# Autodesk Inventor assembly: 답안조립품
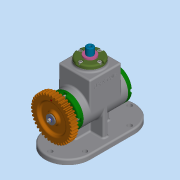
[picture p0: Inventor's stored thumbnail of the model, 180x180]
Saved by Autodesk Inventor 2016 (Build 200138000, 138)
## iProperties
Created: 2020-01
Part Number: 답안조립품
Document SubType Name: Assembly
Designer: MIRAE
Mass: 2018.69 g
Surface Area: 1737.06 cm^2
Volume: 591.723 cm^3
Density: 3.41155 g/cm^3
Author: MIRAE
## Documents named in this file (18)
- C:\Users\MIRAE\Desktop\600104V1003\답안조립품.iam
- C:\Users\MIRAE\Desktop\600104V1003\1-본체.ipt
- C:\Users\MIRAE\Desktop\600104V1003\7-볼트 M4.ipt
- C:\Users\MIRAE\Desktop\600104V1003\12-스프링와셔.ipt
- C:\Users\MIRAE\Desktop\600104V1003\11-평와셔.ipt
- C:\Users\MIRAE\Desktop\600104V1003\10-스퍼기어.ipt
- C:\Users\MIRAE\Desktop\600104V1003\8-오일 실 17 30 5.ipt
- C:\Users\MIRAE\Desktop\600104V1003\4-앞커버.ipt
- C:\Users\MIRAE\Desktop\600104V1003\2-베어링 6203.ipt
- C:\Users\MIRAE\Desktop\600104V1003\3-편심축.ipt
- C:\Users\MIRAE\Desktop\600104V1003\9-키 4x4x12.ipt
- C:\Users\MIRAE\Desktop\600104V1003\5-뒤커버.ipt
- C:\Users\MIRAE\Desktop\600104V1003\15-슬라이더.ipt
- C:\Users\MIRAE\Desktop\600104V1003\17-가변스프링.ipt
- C:\Users\MIRAE\Desktop\600104V1003\14-멈춤링.ipt
- C:\Users\MIRAE\Desktop\600104V1003\13-부시.ipt
- C:\Users\MIRAE\Desktop\600104V1003\6-상부커버.ipt
- C:\Users\MIRAE\Desktop\600104V1003\16-스프링조립용 와셔.ipt
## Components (30 placed, 17 different names)
1. 1-본체:1
2. 7-볼트 M4:1
3. 12-스프링와셔:1
4. 11-평와셔:1
5. 10-스퍼기어:1 — 각도:2
6. 7-볼트 M4:2
7. 7-볼트 M4:3
8. 7-볼트 M4:4
9. 7-볼트 M4:5
10. 8-오일 실 17 30 5:1
11. 4-앞커버:1
12. 2-베어링 6203:1
13. 3-편심축:1 — 각도:1
14. 9-키 4x4x12:1 — 각도:1, 각도:2
15. 2-베어링 6203:2
16. 5-뒤커버:1
17. 7-볼트 M4:6
18. 7-볼트 M4:7
19. 7-볼트 M4:8
20. 7-볼트 M4:9
21. 15-슬라이더:1
22. 17-가변스프링:1
23. 14-멈춤링:1
24. 13-부시:1
25. 6-상부커버:1
26. 7-볼트 M4:10
27. 7-볼트 M4:11
28. 7-볼트 M4:12
29. 7-볼트 M4:13
30. 16-스프링조립용 와셔:1
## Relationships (2: Angle 2)
- 각도:1 [Angle]: 3-편심축:1 ↔ 9-키 4x4x12:1
- 각도:2 [Angle]: 10-스퍼기어:1 ↔ 9-키 4x4x12:1
